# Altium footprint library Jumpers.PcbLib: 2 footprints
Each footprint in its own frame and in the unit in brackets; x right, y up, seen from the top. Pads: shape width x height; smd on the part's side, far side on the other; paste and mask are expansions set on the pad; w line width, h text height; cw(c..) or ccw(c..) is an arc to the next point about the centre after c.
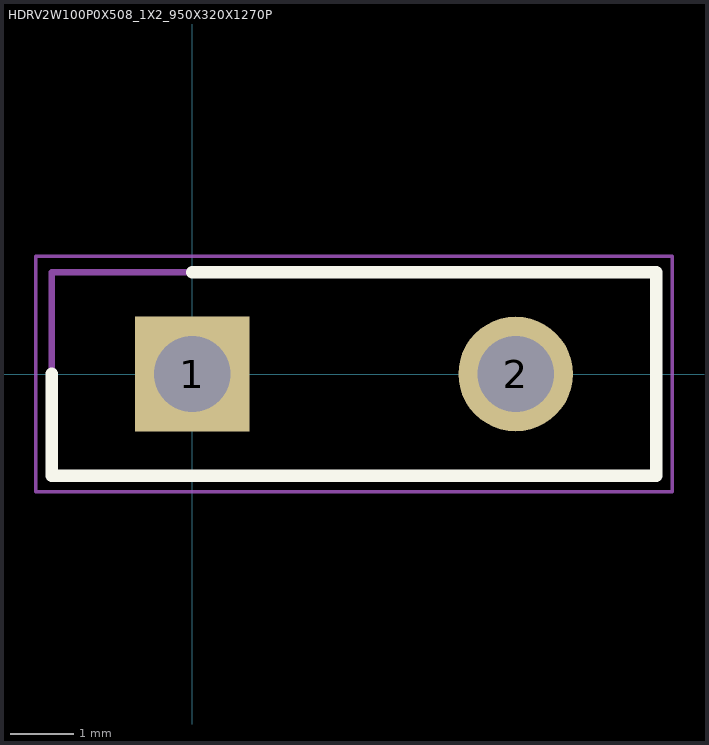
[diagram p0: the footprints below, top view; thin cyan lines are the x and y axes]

## HDRV2W100P0X508_1X2_950X320X1270P [mm]
pads (2):
  rect 1.8x1.8 hole 1.2: 1(0,0)
  round 1.8 hole 1.2: 2(5.08,0)
Top Overlay:
  lines w0.2: -2.21,0 -2.21,-1.6 7.29,-1.6 7.29,1.6 0,1.6
Mechanical 13:
  lines w0.1: -2.21,-1.6 7.29,-1.6 7.29,1.6 -2.21,1.6 -2.21,-1.6
Mechanical 15:
  lines w0.05: -2.46,-1.85 7.54,-1.85 7.54,1.85 -2.46,1.85 -2.46,-1.85
3D body "M50-1920005.stp": height 1.5, standoff -1.5, extent 0,-0.75 2.5,0.75

## PCBComponent_1 [mm]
